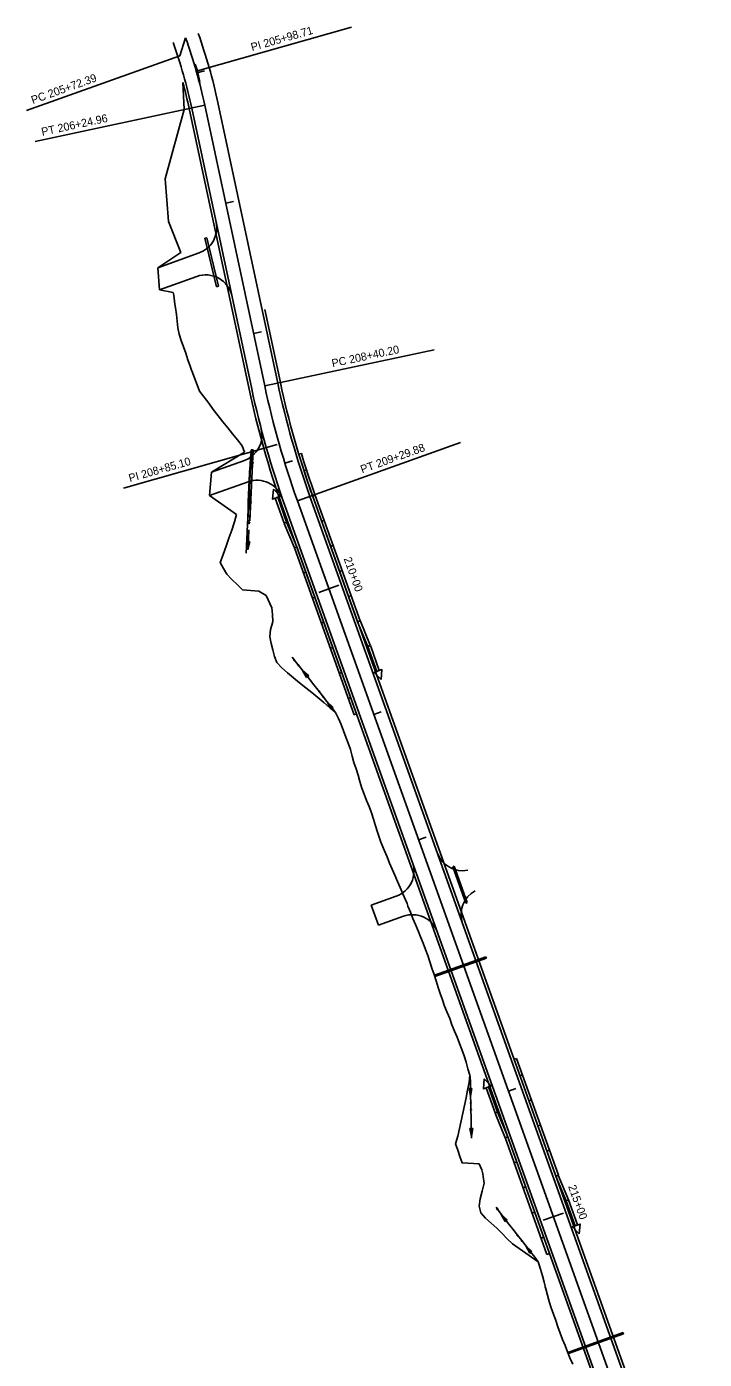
# Model space of a CAD drawing. Extents: x 1051958 to 1052837, y 395840 to 397825.
# Drawn here: x 1051958 to 1052466, y 396826 to 397825 of the extents above; entities that cross this region are included whole.
import ezdxf

# ---------------------------------------------------------------- set-up
doc = ezdxf.new("R2010")
doc.units = 0
for name, color, linetype in [('MOT_PCCB', 7, 'Continuous'), ('MOT_TIAB', 7, 'Continuous'), ('R_Drainage_Temporary', 7, 'Continuous'), ('R_Horz Alg Annot_Detour', 7, 'Continuous'), ('R_Horz Alg Stationing_Detour', 7, 'Continuous'), ('R_Horz Alg_Detour', 7, 'Continuous'), ('R_Proposed Const Limits', 7, 'Continuous'), ('R_Proposed Road_Detour', 7, 'Continuous'), ('R_Shld_Detour', 7, 'Continuous'), ('R_Special Ditch', 7, 'Continuous')]:
    doc.layers.add(name, color=color, linetype=linetype)

msp = doc.modelspace()

# ---------------------------------------------------------------- linework, layer by layer
at = {"layer": 'MOT_PCCB'}
for p, q in [((1052161.99, 397504.49), (1052163.88, 397505.16)), ((1052165.89, 397492.07), (1052167.77, 397492.75)), ((1052172.17, 397473.65), (1052206.03, 397378.98)), ((1052172.35, 397473.14), (1052174.24, 397473.82)), ((1052174.06, 397474.32), (1052207.91, 397379.66)), ((1052150.94, 397452.83), (1052144.21, 397471.67)), ((1052152.83, 397453.51), (1052146.09, 397472.34)), ((1052152.83, 397453.51), (1052150.94, 397452.83)), ((1052152.83, 397453.51), (1052150.98, 397452.74)), ((1052160.5, 397435.01), (1052152.83, 397453.51)), ((1052179.09, 397454.31), (1052180.97, 397454.99)), ((1052158.66, 397434.25), (1052150.98, 397452.74)), ((1052160.5, 397435.01), (1052158.62, 397434.34)), ((1052203.4, 397309.11), (1052158.62, 397434.34)), ((1052160.5, 397435.01), (1052158.66, 397434.25)), ((1052205.29, 397309.78), (1052160.5, 397435.01)), ((1052185.82, 397435.48), (1052187.71, 397436.15)), ((1052167.24, 397416.18), (1052165.35, 397415.51)), ((1052192.56, 397416.65), (1052194.44, 397417.32)), ((1052173.97, 397397.35), (1052172.09, 397396.67)), ((1052199.29, 397397.82), (1052201.18, 397398.49)), ((1052180.71, 397378.52), (1052178.82, 397377.84)), ((1052206.03, 397378.98), (1052207.87, 397379.75)), ((1052206.03, 397378.98), (1052207.91, 397379.66)), ((1052206.03, 397378.98), (1052213.7, 397360.49)), ((1052207.87, 397379.75), (1052215.55, 397361.26)), ((1052187.44, 397359.68), (1052185.56, 397359.01)), ((1052213.7, 397360.49), (1052215.55, 397361.26)), ((1052213.7, 397360.49), (1052215.59, 397361.16)), ((1052213.7, 397360.49), (1052220.44, 397341.66)), ((1052215.59, 397361.16), (1052222.32, 397342.33)), ((1052194.18, 397340.85), (1052192.29, 397340.18)), ((1052220.44, 397341.66), (1052222.32, 397342.33)), ((1052200.91, 397322.02), (1052199.03, 397321.35)), ((1052205.29, 397309.78), (1052203.4, 397309.11)), ((1052323.41, 397050.75), (1052325.29, 397051.42)), ((1052323.41, 397050.75), (1052354.73, 396963.18)), ((1052325.29, 397051.42), (1052356.61, 396963.85)), ((1052327.79, 397038.51), (1052329.67, 397039.18)), ((1052309.1, 397010.59), (1052302.36, 397029.42)), ((1052310.98, 397011.26), (1052304.25, 397030.09)), ((1052334.52, 397019.68), (1052336.41, 397020.35)), ((1052310.98, 397011.26), (1052309.1, 397010.59)), ((1052310.98, 397011.26), (1052309.14, 397010.49)), ((1052316.81, 396992), (1052309.14, 397010.49)), ((1052318.66, 396992.76), (1052310.98, 397011.26)), ((1052341.26, 397000.85), (1052343.14, 397001.52)), ((1052318.66, 396992.76), (1052316.78, 396992.09)), ((1052348.09, 396904.52), (1052316.78, 396992.09)), ((1052318.66, 396992.76), (1052316.81, 396992)), ((1052349.98, 396905.2), (1052318.66, 396992.76)), ((1052325.39, 396973.93), (1052323.51, 396973.26)), ((1052347.99, 396982.01), (1052349.88, 396982.69)), ((1052354.73, 396963.18), (1052356.57, 396963.95)), ((1052354.73, 396963.18), (1052356.61, 396963.85)), ((1052356.57, 396963.95), (1052364.25, 396945.45)), ((1052332.13, 396955.1), (1052330.25, 396954.43)), ((1052354.73, 396963.18), (1052362.4, 396944.69)), ((1052362.4, 396944.69), (1052364.25, 396945.45)), ((1052362.4, 396944.69), (1052364.29, 396945.36)), ((1052362.4, 396944.69), (1052369.14, 396925.85)), ((1052364.29, 396945.36), (1052371.02, 396926.53)), ((1052338.86, 396936.27), (1052336.98, 396935.59)), ((1052369.14, 396925.85), (1052371.02, 396926.53)), ((1052345.6, 396917.44), (1052343.71, 396916.76)), ((1052349.98, 396905.2), (1052348.09, 396904.52))]:
    msp.add_line(p, q, dxfattribs=at)
for radius, start in [(662.07, 196.86722), (660.07, 196.85869)]:
    msp.add_arc((1052795.58, 397696.59), radius, start, 199.67806, dxfattribs=at)
at = {"layer": 'MOT_TIAB'}
for points in [[(1052142.9, 397478.29), (1052148.1, 397473.06), (1052142.2, 397470.95)], [(1052223.63, 397335.71), (1052218.43, 397340.94), (1052224.33, 397343.05)], [(1052301.06, 397036.04), (1052306.26, 397030.81), (1052300.35, 397028.7)], [(1052372.33, 396919.9), (1052367.13, 396925.13), (1052373.03, 396927.25)]]:
    msp.add_lwpolyline(points, close=True, dxfattribs=at)
at = {"layer": 'R_Drainage_Temporary'}
for p, q in [((1052091.58, 397666.49), (1052093.03, 397666.84)), ((1052091.58, 397666.49), (1052100.29, 397630.13)), ((1052093.03, 397666.84), (1052101.75, 397630.48)), ((1052101.75, 397630.48), (1052100.29, 397630.13)), ((1052126.19, 397507.92), (1052123.82, 397454.56)), ((1052127.69, 397507.86), (1052125.32, 397454.5)), ((1052126.19, 397507.92), (1052127.69, 397507.86)), ((1052123.82, 397454.56), (1052125.32, 397454.5)), ((1052277.43, 397195.2), (1052278.37, 397195.54)), ((1052277.43, 397195.2), (1052287.25, 397167.92)), ((1052278.37, 397195.54), (1052288.2, 397168.26)), ((1052287.25, 397167.92), (1052288.2, 397168.26)), ((1052302.29, 397127.63), (1052263.68, 397113.82)), ((1052302.63, 397126.69), (1052264.02, 397112.88)), ((1052302.29, 397127.63), (1052302.63, 397126.69)), ((1052264.02, 397112.88), (1052263.68, 397113.82)), ((1052405.19, 396845.82), (1052363.76, 396831.01)), ((1052405.53, 396844.88), (1052364.1, 396830.06)), ((1052405.19, 396845.82), (1052405.53, 396844.88)), ((1052364.1, 396830.06), (1052363.76, 396831.01))]:
    msp.add_line(p, q, dxfattribs=at)
at = {"layer": 'R_Horz Alg Annot_Detour'}
for p, q in [((1052072.58, 397803.31), (1052077.06, 397816.83)), ((1052084.11, 397797.12), (1052085.92, 397792.04)), ((1052085.92, 397792.04), (1052087.74, 397783.54))]:
    msp.add_line(p, q, dxfattribs=at)
for points in [[(1052085.92, 397792.04), (1052201.35, 397824.85)], [(1052072.58, 397803.31), (1051957.81, 397762.27)], [(1052091.42, 397766.29), (1051964.29, 397739.14)], [(1052136.37, 397555.8), (1052263.51, 397582.96)], [(1052160.88, 397469.61), (1052283.28, 397513.38)], [(1052145.75, 397511.89), (1052030.33, 397479.08)]]:
    msp.add_lwpolyline(points, dxfattribs=at)
at = {"layer": 'R_Horz Alg Stationing_Detour'}
for points in [[(1052091.22, 397792.14), (1052085.44, 397790.52)], [(1052112.96, 397694.16), (1052107.09, 397692.91)], [(1052133.85, 397596.37), (1052127.98, 397595.11)], [(1052157.18, 397499.72), (1052151.44, 397497.95)], [(1052192.02, 397406.27), (1052176.96, 397400.88)], [(1052223.81, 397311.44), (1052218.16, 397309.42)], [(1052257.49, 397217.28), (1052251.84, 397215.26)], [(1052291.16, 397123.12), (1052285.51, 397121.1)], [(1052324.83, 397028.96), (1052319.18, 397026.94)], [(1052360.39, 396935.47), (1052345.32, 396930.08)], [(1052392.18, 396840.64), (1052386.53, 396838.62)]]:
    msp.add_lwpolyline(points, dxfattribs=at)
at = {"layer": 'R_Horz Alg_Detour'}
for p, q in [((1052091.42, 397766.29), (1052136.37, 397555.8)), ((1052160.88, 397469.61), (1052454.82, 396647.66))]:
    msp.add_line(p, q, dxfattribs=at)
for centre, radius, start, end in [((1051704.99, 397683.77), 395.14, 12.05527, 19.67805), ((1052795.58, 397696.59), 674.07, 192.05527, 199.67806)]:
    msp.add_arc(centre, radius, start, end, dxfattribs=at)
at = {"layer": 'R_Proposed Const Limits'}
for p, q in [((1052076.04, 397763.05), (1052074.97, 397783.33)), ((1052096.51, 397491.06), (1052121.14, 397506.08)), ((1052094.94, 397473.51), (1052115.33, 397459.39)), ((1052137.53, 397398.53), (1052141.8, 397389.44))]:
    msp.add_line(p, q, dxfattribs=at)
for points in [[(1052076.04, 397763.05), (1052061.68, 397711.19), (1052064.28, 397679.19), (1052073.44, 397655.92), (1052056.23, 397644.45)], [(1052057.49, 397627.91), (1052067.79, 397625.85)], [(1052067.79, 397625.85), (1052068.08, 397623.76), (1052068.71, 397619.33), (1052069.02, 397617.08), (1052069.4, 397614.37), (1052070.09, 397609.4), (1052070.67, 397604.41), (1052071.13, 397599.4), (1052072.1, 397594.49), (1052073.78, 397589.74), (1052075.47, 397584.99), (1052077.18, 397580.24), (1052078.81, 397575.47), (1052080.45, 397570.71), (1052081.54, 397567.73), (1052082.19, 397565.97), (1052083.93, 397561.23), (1052085.69, 397556.49), (1052087.49, 397551.76), (1052090.86, 397547.37), (1052094.45, 397542.78), (1052097.72, 397538.06), (1052101.34, 397533.46), (1052104.98, 397528.9), (1052108.64, 397524.38), (1052112.33, 397519.91), (1052115.93, 397515.45), (1052119.36, 397510.98), (1052121.14, 397506.08)], [(1052115.33, 397459.39), (1052113.75, 397453.82), (1052111.66, 397447.69), (1052109.57, 397441.63), (1052107.54, 397435.6), (1052105.33, 397429.49), (1052103.49, 397424.52), (1052103.06, 397423.37), (1052105.54, 397418.95), (1052108.07, 397414.55), (1052111.74, 397410.55), (1052115.87, 397406.71), (1052119.81, 397402.81), (1052131.93, 397401.84), (1052137.53, 397398.53)], [(1052141.8, 397389.44), (1052142.32, 397384.31), (1052142.34, 397379.01), (1052141.6, 397376.41), (1052140.59, 397373.07), (1052140.1, 397367.59), (1052141.33, 397362.72), (1052142.55, 397357.85), (1052143.76, 397352.97), (1052145.46, 397348.27), (1052149.32, 397344.33), (1052153.57, 397340.55), (1052157.98, 397336.81), (1052162.58, 397333.15), (1052167.1, 397329.46), (1052171.61, 397325.76), (1052176.11, 397322.06), (1052180.59, 397318.35), (1052185.03, 397314.62), (1052189.12, 397310.78)], [(1052191.68, 397306.38), (1052193.76, 397301.82), (1052195.54, 397297.14), (1052197.27, 397292.45), (1052198.99, 397287.76), (1052200.63, 397283.03), (1052201.97, 397278.2), (1052203.31, 397273.37), (1052204.94, 397268.65), (1052206.48, 397263.88), (1052207.82, 397259.05), (1052209.16, 397254.22), (1052210.89, 397249.53), (1052212.81, 397244.91), (1052214.8, 397240.31), (1052216.45, 397235.59), (1052217.89, 397230.8), (1052219.34, 397226), (1052220.88, 397221.24), (1052222.49, 397216.51), (1052223.57, 397213.65), (1052224.25, 397211.83), (1052226.09, 397207.18), (1052228.11, 397202.59), (1052230.05, 397197.97), (1052232.01, 397193.36), (1052234.03, 397188.78), (1052235.98, 397184.16), (1052237.92, 397179.55), (1052239.96, 397174.97), (1052242, 397170.38), (1052243.13, 397167.54), (1052243.84, 397165.73), (1052245.66, 397161.07), (1052247.48, 397156.41), (1052249.45, 397151.81), (1052251.48, 397147.22), (1052253.34, 397142.58), (1052255.16, 397137.92), (1052256.98, 397133.26), (1052258.66, 397128.55), (1052260.14, 397123.77), (1052261.73, 397119.03), (1052263.36, 397114.3), (1052264.87, 397109.53), (1052266.37, 397104.76), (1052268.01, 397100.03), (1052269.64, 397095.31), (1052271.27, 397090.58), (1052273.16, 397085.95), (1052275.13, 397081.34), (1052276.76, 397076.61), (1052278.61, 397071.97), (1052280.62, 397067.37), (1052282.41, 397062.7), (1052284.2, 397058.03), (1052285.93, 397053.34), (1052287.38, 397048.55), (1052288.83, 397043.76), (1052290.28, 397038.97)], [(1052290.28, 397038.97), (1052289.62, 397033.42), (1052288.55, 397027.73), (1052287.37, 397022), (1052286.15, 397016.25), (1052284.93, 397010.5), (1052283.71, 397004.76), (1052282.49, 396999.01), (1052281.27, 396993.27), (1052279.54, 396987.33), (1052281.12, 396982.59), (1052282.74, 396977.86), (1052284.36, 396973.13), (1052297.12, 396972.38), (1052299.2, 396967.81), (1052299.95, 396964.84), (1052300.22, 396962.87), (1052300.93, 396957.82), (1052299.46, 396951.98), (1052298.07, 396946.17), (1052297.34, 396940.6), (1052298.37, 396935.66), (1052301.99, 396931.64), (1052306.3, 396927.87), (1052310.59, 396924.1), (1052314.47, 396920.17), (1052318.34, 396916.25), (1052322.25, 396912.34), (1052327.18, 396908.79), (1052332.29, 396905.31), (1052341.49, 396898.97)], [(1052341.49, 396898.97), (1052341.76, 396898.08), (1052343.23, 396893.29), (1052344.64, 396888.48), (1052345.89, 396883.62), (1052346.65, 396880.64), (1052346.76, 396880.2), (1052347.13, 396878.76), (1052348.38, 396873.89), (1052349.81, 396869.09), (1052351.27, 396864.31), (1052352.95, 396859.59), (1052352.97, 396859.54), (1052354.67, 396854.9), (1052356.28, 396850.17), (1052358, 396845.47), (1052359.72, 396840.78), (1052361.83, 396836.22), (1052363.55, 396831.53), (1052365.33, 396826.85), (1052367.38, 396822.27)]]:
    msp.add_lwpolyline(points, dxfattribs=at)
at = {"layer": 'R_Proposed Road_Detour'}
for p, q in [((1052081.64, 397764.21), (1052126.6, 397553.72)), ((1052081.64, 397764.21), (1052126.6, 397553.72)), ((1052101.2, 397768.38), (1052146.15, 397557.89)), ((1052056.23, 397644.45), (1052087.12, 397655.5)), ((1052056.23, 397644.45), (1052057.49, 397627.91)), ((1052057.49, 397627.91), (1052085.45, 397637.91)), ((1052096.51, 397491.06), (1052121.09, 397499.85)), ((1052096.51, 397491.06), (1052094.94, 397473.51)), ((1052094.94, 397473.51), (1052123.94, 397483.88)), ((1052151.46, 397466.24), (1052445.4, 396644.3)), ((1052151.46, 397466.24), (1052445.4, 396644.3)), ((1052170.29, 397472.97), (1052464.23, 396651.03)), ((1052216.2, 397166.4), (1052235.04, 397173.14)), ((1052216.2, 397166.4), (1052221.59, 397151.34)), ((1052221.59, 397151.34), (1052240.42, 397158.07))]:
    msp.add_line(p, q, dxfattribs=at)
for centre, radius, start, end in [((1051704.99, 397683.77), 385.14, 12.05527, 19.67806), ((1051704.99, 397683.77), 405.14, 12.05527, 19.67806), ((1052080.39, 397674.33), 20, 289.67806, 12.05527), ((1052092.19, 397619.08), 20, 12.05527, 109.67806), ((1052795.58, 397696.59), 684.07, 192.05527, 199.67806), ((1052795.58, 397696.59), 684.07, 192.05527, 199.67806), ((1052795.58, 397696.59), 664.07, 192.05527, 199.67806), ((1052114.36, 397518.68), 20, 289.67806, 14.63627), ((1052130.67, 397465.04), 20, 19.19994, 109.67806), ((1052284.8, 397212.18), 20, 199.67806, 281.05113), ((1052228.3, 397191.97), 20, 289.67806, 19.67806), ((1052303.66, 397159.45), 20, 118.30498, 199.67806), ((1052247.16, 397139.24), 20, 19.67806, 109.67806)]:
    msp.add_arc(centre, radius, start, end, dxfattribs=at)
at = {"layer": 'R_Shld_Detour'}
for p, q in [((1052079.69, 397763.79), (1052124.64, 397553.3)), ((1052136.42, 397613.06), (1052148.11, 397558.31)), ((1052172.17, 397473.65), (1052466.12, 396651.7)), ((1052149.58, 397465.56), (1052443.52, 396643.62))]:
    msp.add_line(p, q, dxfattribs=at)
for centre, radius, start, end in [((1051704.99, 397683.77), 383.14, 12.05527, 15.06222), ((1052795.58, 397696.59), 686.07, 192.05527, 199.67806), ((1052795.58, 397696.59), 662.07, 192.05527, 199.67806)]:
    msp.add_arc(centre, radius, start, end, dxfattribs=at)
at = {"layer": 'R_Special Ditch'}
for p, q in [((1052127.71, 397498.93), (1052125.59, 397499.07)), ((1052125.59, 397499.07), (1052126.27, 397493.01)), ((1052126.27, 397493.01), (1052127.71, 397498.93)), ((1052126.21, 397468.97), (1052124.09, 397469.03)), ((1052124.09, 397469.03), (1052124.97, 397463)), ((1052124.97, 397463), (1052126.21, 397468.97)), ((1052125.12, 397438.93), (1052123.01, 397439.03)), ((1052123.01, 397439.03), (1052123.77, 397432.99)), ((1052123.77, 397432.99), (1052125.12, 397438.93)), ((1052164.79, 397342.42), (1052167.69, 397337.07)), ((1052169.35, 397338.38), (1052164.79, 397342.42)), ((1052167.69, 397337.07), (1052169.35, 397338.38)), ((1052183.33, 397318.79), (1052186.16, 397313.39)), ((1052187.83, 397314.68), (1052183.33, 397318.79)), ((1052186.16, 397313.39), (1052187.83, 397314.68)), ((1052291.77, 397028.95), (1052289.66, 397028.91)), ((1052289.66, 397028.91), (1052290.84, 397022.93)), ((1052290.84, 397022.93), (1052291.77, 397028.95)), ((1052292.4, 396998.92), (1052290.29, 396998.88)), ((1052290.29, 396998.88), (1052291.47, 396992.9)), ((1052291.47, 396992.9), (1052292.4, 396998.92)), ((1052313.76, 396934.47), (1052316.63, 396929.09)), ((1052318.29, 396930.4), (1052313.76, 396934.47)), ((1052316.63, 396929.09), (1052318.29, 396930.4)), ((1052332.27, 396910.81), (1052335.14, 396905.43)), ((1052336.8, 396906.74), (1052332.27, 396910.81)), ((1052335.14, 396905.43), (1052336.8, 396906.74))]:
    msp.add_line(p, q, dxfattribs=at)
for points in [[(1052126.22, 397507.52), (1052126.09, 397506.29), (1052125.78, 397502.01), (1052125.41, 397496.5), (1052125.26, 397494.23), (1052125.07, 397490.97), (1052125, 397489.79), (1052124.76, 397485.42), (1052124.49, 397479.85), (1052124.25, 397474.26), (1052124.04, 397468.65), (1052124, 397467.46), (1052123.87, 397463.02), (1052123.73, 397457.37), (1052123.53, 397451.94), (1052123.31, 397446.54), (1052123.07, 397441.15), (1052122.82, 397435.75), (1052122.55, 397430.34)], [(1052127.34, 397507.97), (1052127.21, 397506.75), (1052126.89, 397502.47), (1052126.52, 397496.96), (1052126.38, 397494.68), (1052126.28, 397493.01)], [(1052124.39, 397477.57), (1052124.39, 397477.54)], [(1052125.5, 397477.99), (1052125.36, 397474.72), (1052125.15, 397469.11), (1052125.12, 397467.92), (1052124.98, 397463.48), (1052124.97, 397463)], [(1052124.46, 397447.97), (1052124.42, 397447), (1052124.18, 397441.61), (1052123.93, 397436.21), (1052123.77, 397432.99)], [(1052156.86, 397352.34), (1052160.17, 397348.22), (1052163.47, 397344.09), (1052165.29, 397341.79), (1052166.76, 397339.95), (1052170.03, 397335.81), (1052173.29, 397331.67), (1052176.54, 397327.52), (1052179.78, 397323.37), (1052183, 397319.21), (1052186.21, 397315.05), (1052186.92, 397314.13), (1052189.34, 397310.86), (1052191.68, 397306.38)], [(1052174.09, 397330.65), (1052173.29, 397331.67), (1052170.03, 397335.81), (1052166.76, 397339.95), (1052165.29, 397341.79), (1052164.79, 397342.42)], [(1052174.11, 397330.62), (1052174.09, 397330.65)], [(1052191.68, 397306.38), (1052189.34, 397310.86), (1052186.92, 397314.13), (1052186.21, 397315.05), (1052183.33, 397318.79)], [(1052290.53, 397037.93), (1052290.53, 397037.93), (1052290.61, 397033.78), (1052290.72, 397028.51), (1052290.83, 397023.24), (1052290.95, 397017.97), (1052291.06, 397012.7), (1052291.17, 397007.42), (1052291.28, 397002.15), (1052291.39, 396996.88), (1052291.5, 396991.61)], [(1052290.53, 397037.93), (1052290.53, 397037.93), (1052290.61, 397033.78), (1052290.72, 397028.51), (1052290.83, 397023.24), (1052290.84, 397022.93)], [(1052291.16, 397007.94), (1052291.16, 397007.9)], [(1052291.16, 397007.9), (1052291.17, 397007.42), (1052291.28, 397002.15), (1052291.39, 396996.88), (1052291.47, 396992.9)], [(1052310, 396939.82), (1052312.92, 396935.55), (1052316.16, 396931.4), (1052319.41, 396927.25), (1052322.65, 396923.1), (1052325.9, 396918.95), (1052329.15, 396914.8), (1052332.39, 396910.66), (1052335.64, 396906.51), (1052338.89, 396902.36), (1052341.49, 396898.98)], [(1052323.01, 396922.65), (1052322.65, 396923.1), (1052319.41, 396927.25), (1052316.16, 396931.4), (1052313.76, 396934.47)], [(1052323.03, 396922.62), (1052323.01, 396922.65)], [(1052341.49, 396898.98), (1052338.89, 396902.36), (1052335.64, 396906.51), (1052332.39, 396910.66), (1052332.27, 396910.81)]]:
    msp.add_lwpolyline(points, dxfattribs=at)
for centre in [(1052125.77, 397483.01), (1052126.03, 397488.01), (1052124.71, 397452.99), (1052124.89, 397458), (1052158.51, 397350.23), (1052161.64, 397346.32), (1052177.15, 397326.67), (1052180.23, 397322.72), (1052290.98, 397017.93), (1052291.09, 397012.92), (1052310.84, 396938.53), (1052326.07, 396918.68), (1052329.16, 396914.73)]:
    msp.add_circle(centre, 0.375, dxfattribs=at)

# ---------------------------------------------------------------- texts
at = {"layer": 'R_Horz Alg Annot_Detour'}
for s, rotation, p in [('PI 205+98.71', 15.86666, (1052126.95, 397806.82)), ('PC 205+72.39', 19.67805, (1051962.45, 397767.11)), ('PT 206+24.96', 12.05527, (1051969.53, 397743.33)), ('PC 208+40.20', 12.05527, (1052187.3, 397569.75)), ('PT 209+29.88', 19.67806, (1052209.45, 397490.16)), ('PI 208+85.10', 15.86666, (1052035.28, 397483.61))]:
    msp.add_text(s, height=6, rotation=rotation, dxfattribs=at).set_placement(p)
at = {"layer": 'R_Horz Alg Stationing_Detour'}
for s, p in [('210+00', (1052195.5, 397426.25)), ('215+00', (1052363.86, 396955.45))]:
    msp.add_text(s, height=6, rotation=289.67806, dxfattribs=at).set_placement(p)

doc.saveas('drawing.dxf')
